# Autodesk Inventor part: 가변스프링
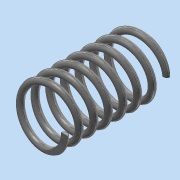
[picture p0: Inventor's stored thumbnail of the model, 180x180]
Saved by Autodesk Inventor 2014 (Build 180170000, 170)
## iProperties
Created: 2022-08
Part Number: 가변스프링
Material: 스테인레스 스틸
Document SubType Name: Modeling
Designer: dg
Density: 8.08 g/cm^3
Appearance: 반연마
Mass: 70.524 g
Surface Area: 88.3602 cm^2
Volume: 8.72822 cm^3
Author: dg
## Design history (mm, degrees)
sketch "스케치1"
  geometry: L1 (0, 0)-(16, 0); L2 (0, 0)-(0, 64); L3 (0, 64)-(16, 64); C1 r 2 at (16, 0)
  constraints: 6 end point, 1 centre point, 1 coincident, 1 horizontal, 1 parallel, 1 perpendicular, 1 vertical
  dimensions: "d0" = 4 diameter of C1; "d1" = 32 diameter of C1.centre L2; "d2" = 64 distance of L1.start L2.end (derived)
feature "코일1" pitch "d3" = 10; turns "d5" = 7; dims "d4" = 64 (= d2), "d6" = 0, angle "d7" = 90 deg, angle "d8" = 90 deg, "d9" = 0, "d10" = 0
node "작업 평면1"
node "작업 평면2"
feature "분할1"
feature "분할2"
node "솔리드1"
other parameters: "d11" = 90 deg
